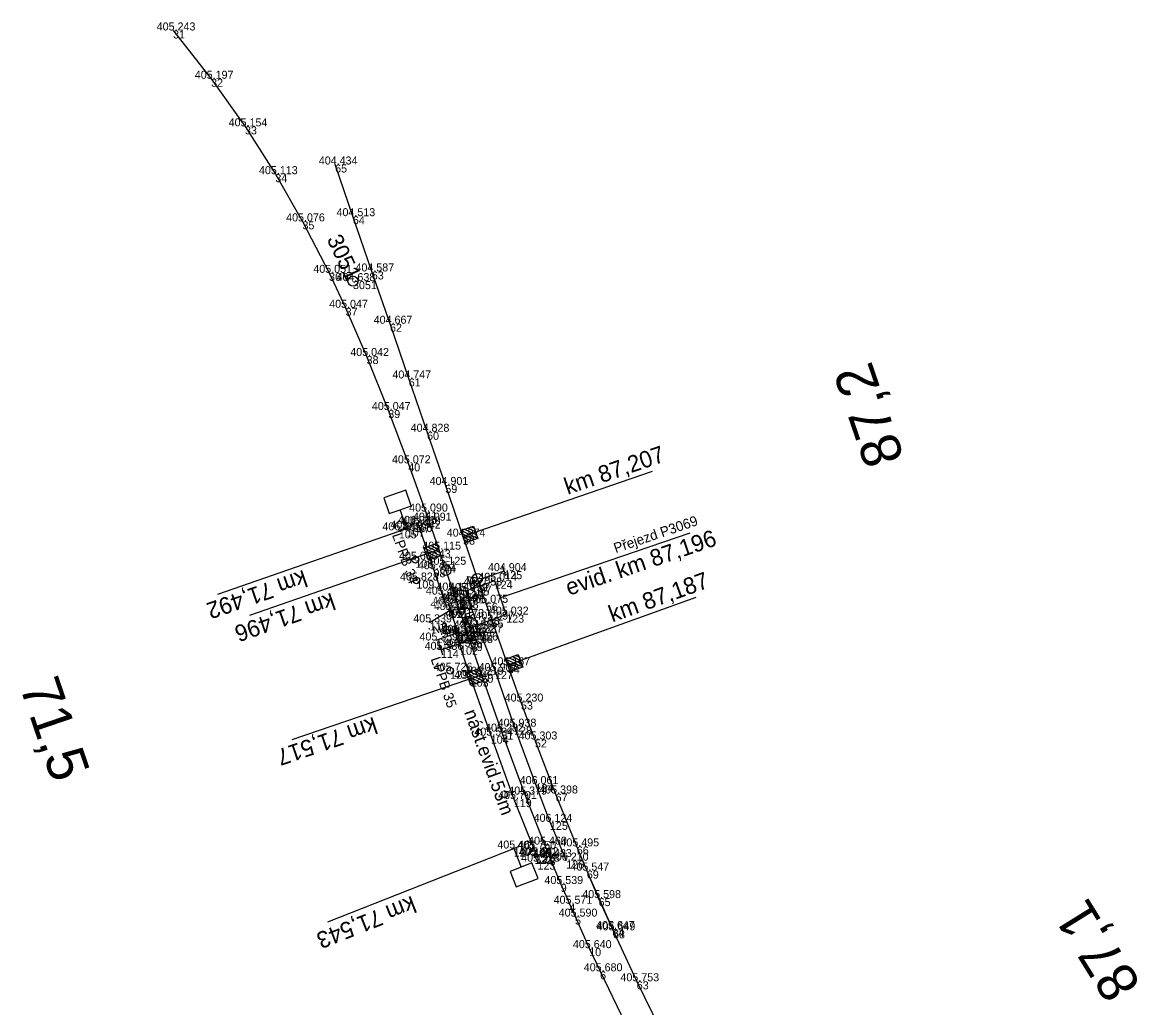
# Model space of a CAD drawing. Extents: x -663503 to -663109, y -1005607 to -1005191.
# Drawn here: x -663503.2 to -663335.9, y -1005338.4 to -1005190.7 of the extents above; entities that cross this region are included whole.
import ezdxf

# ---------------------------------------------------------------- set-up
doc = ezdxf.new("R2010")
doc.units = 0
for name, color, linetype in [('Vrstva 1', 7, 'Continuous'), ('Vrstva 14', 7, 'Continuous'), ('Vrstva 17', 7, 'Continuous'), ('Vrstva 27', 7, 'Continuous'), ('Vrstva 3', 7, 'Continuous'), ('Vrstva 4', 7, 'Continuous'), ('Vrstva 51', 7, 'Continuous'), ('Vrstva 60', 7, 'Continuous'), ('Vrstva 61', 7, 'Continuous'), ('Vrstva 63', 7, 'Continuous'), ('Vrstva 7', 7, 'Continuous')]:
    doc.layers.add(name, color=color, linetype=linetype)

msp = doc.modelspace()

# ---------------------------------------------------------------- linework, layer by layer
at = {"layer": 'Vrstva 1'}
for points in [[(-663480.6, -1005191.9), (-663474.89, -1005199.14), (-663469.81, -1005206.28), (-663465.26, -1005213.44), (-663461.19, -1005220.52), (-663457.21, -1005228.23), (-663454.72, -1005233.47), (-663451.57, -1005240.7), (-663448.32, -1005248.79), (-663445.32, -1005256.78), (-663442.74, -1005264.01), (-663442.26, -1005265.38), (-663440.75, -1005269.72), (-663439.97, -1005271.99), (-663438.65, -1005275.86), (-663438.1, -1005277.49), (-663437.3, -1005279.82), (-663436.51, -1005282.15), (-663435.97, -1005283.72), (-663434.35, -1005288.47), (-663431.35, -1005296.99), (-663427.86, -1005306.43), (-663424.9, -1005313.94), (-663424.14, -1005315.79), (-663422.45, -1005319.84), (-663421.16, -1005322.8), (-663420.31, -1005324.72), (-663418.18, -1005329.45), (-663416.55, -1005332.92), (-663412.77, -1005340.68)], [(-663407.43, -1005341.75), (-663411.05, -1005334.42), (-663414.7, -1005326.58), (-663416.77, -1005321.95), (-663420.04, -1005314.2), (-663423.22, -1005306.27), (-663426.32, -1005298.17), (-663428.42, -1005292.49), (-663430.38, -1005287.06), (-663432.81, -1005280.21), (-663433.69, -1005277.69), (-663434.59, -1005275.1), (-663437.1, -1005267.77), (-663439.76, -1005260.02), (-663442.5, -1005252.05), (-663445.25, -1005244.06), (-663448.06, -1005235.86), (-663450.79, -1005228.02), (-663453.63, -1005219.74), (-663456.29, -1005211.99)], [(-663414.61, -1005326.78), (-663418.54, -1005317.83)]]:
    msp.add_lwpolyline(points, dxfattribs=at)
at = {"layer": 'Vrstva 14'}
for points in [[(-663443.83, -1005265.96), (-663441.53, -1005272.66), (-663440.24, -1005276.46), (-663439.54, -1005278.4)], [(-663438.18, -1005282.37), (-663437.55, -1005284.27), (-663435.95, -1005289.06), (-663432.95, -1005297.6), (-663429.49, -1005307.1), (-663426.51, -1005314.57), (-663426.15, -1005315.52), (-663426.39, -1005315.63), (-663425.94, -1005316.49)]]:
    msp.add_lwpolyline(points, dxfattribs=at)
at = {"layer": 'Vrstva 17'}
msp.add_line((-663446.74, -1005266.83), (-663444.4, -1005265.86), dxfattribs=at)
msp.add_lwpolyline([(-663434.53, -1005282.14), (-663432.31, -1005287.92), (-663429.46, -1005296.25), (-663426.26, -1005304.86), (-663424.07, -1005310.52), (-663421.63, -1005316.33)], dxfattribs=at)
at = {"layer": 'Vrstva 27'}
for p, q in [((-663444.28, -1005271.18), (-663444.24, -1005271.28)), ((-663439.06, -1005287.83), (-663439.03, -1005287.92))]:
    msp.add_line(p, q, dxfattribs=at)
for centre in [(-663444.26, -1005271.23), (-663439.05, -1005287.87)]:
    msp.add_circle(centre, 0.5, dxfattribs=at)
at = {"layer": 'Vrstva 3'}
for p, q in [((-663408.73, -1005258.03), (-663437.1, -1005267.77)), ((-663435.06, -1005267.57), (-663436.92, -1005266.65)), ((-663435.23, -1005267.06), (-663436.42, -1005266.48)), ((-663435.4, -1005266.56), (-663435.92, -1005266.31)), ((-663434.88, -1005268.07), (-663437.43, -1005266.83)), ((-663435.39, -1005268.24), (-663437.25, -1005267.33)), ((-663435.89, -1005268.41), (-663437.08, -1005267.83)), ((-663436.39, -1005268.58), (-663436.91, -1005268.33)), ((-663469.1, -1005279.53), (-663440.75, -1005269.72)), ((-663442.97, -1005269.43), (-663440.42, -1005270.67)), ((-663442.79, -1005269.93), (-663440.92, -1005270.84)), ((-663442.47, -1005269.26), (-663440.6, -1005270.17)), ((-663441.96, -1005269.09), (-663440.77, -1005269.67)), ((-663441.46, -1005268.91), (-663440.94, -1005269.16)), ((-663442.62, -1005270.43), (-663441.42, -1005271.02)), ((-663442.45, -1005270.94), (-663441.93, -1005271.19)), ((-663402.17, -1005276.87), (-663430.38, -1005287.06)), ((-663428.16, -1005287.32), (-663430.72, -1005286.12)), ((-663428.66, -1005287.5), (-663430.54, -1005286.62)), ((-663428.34, -1005286.82), (-663430.23, -1005285.94)), ((-663428.52, -1005286.32), (-663429.73, -1005285.76)), ((-663428.7, -1005285.83), (-663429.23, -1005285.58)), ((-663436.57, -1005288.17), (-663434.03, -1005289.42)), ((-663436.07, -1005288), (-663434.2, -1005288.91)), ((-663435.56, -1005287.83), (-663434.37, -1005288.41)), ((-663435.06, -1005287.66), (-663434.54, -1005287.91)), ((-663429.16, -1005287.68), (-663430.36, -1005287.12)), ((-663429.66, -1005287.86), (-663430.18, -1005287.62)), ((-663462.74, -1005298.18), (-663434.35, -1005288.47)), ((-663436.4, -1005288.67), (-663434.53, -1005289.59)), ((-663436.22, -1005289.17), (-663435.03, -1005289.76)), ((-663436.05, -1005289.68), (-663435.53, -1005289.93))]:
    msp.add_line(p, q, dxfattribs=at)
for points in [[(-663436.78, -1005268.72), (-663437.43, -1005266.83), (-663435.53, -1005266.18), (-663434.88, -1005268.07)], [(-663441.08, -1005268.78), (-663440.42, -1005270.67), (-663442.31, -1005271.32), (-663442.97, -1005269.43)], [(-663430.04, -1005288), (-663430.72, -1005286.12), (-663428.84, -1005285.44), (-663428.16, -1005287.32)], [(-663434.68, -1005287.52), (-663434.03, -1005289.42), (-663435.92, -1005290.06), (-663436.57, -1005288.17)]]:
    msp.add_lwpolyline(points, close=True, dxfattribs=at)
at = {"layer": 'Vrstva 4'}
for p, q in [((-663403.11, -1005267.23), (-663431.5, -1005276.92)), ((-663430.67, -1005273.67), (-663431.17, -1005272.2)), ((-663435.27, -1005274.64), (-663435.71, -1005274.42)), ((-663436.06, -1005283.04), (-663435.62, -1005283.26)), ((-663440.66, -1005284), (-663440.17, -1005285.48))]:
    msp.add_line(p, q, dxfattribs=at)
for points in [[(-663430.92, -1005272.94), (-663434.21, -1005274.06), (-663435.79, -1005275.64), (-663436.44, -1005273.75), (-663434.21, -1005274.06)], [(-663432.36, -1005274.38), (-663436.75, -1005275.94), (-663436.5, -1005276.59), (-663434.99, -1005281), (-663430.63, -1005279.46), (-663432.36, -1005274.38)], [(-663439.28, -1005277.96), (-663437.72, -1005282.62), (-663435.9, -1005282), (-663436.06, -1005281.51), (-663437.45, -1005277.35), (-663439.28, -1005277.96)], [(-663440.42, -1005284.74), (-663437.12, -1005283.62), (-663435.54, -1005282.04), (-663434.89, -1005283.93), (-663437.12, -1005283.62)]]:
    msp.add_lwpolyline(points, dxfattribs=at)
for centre in [(-663435.49, -1005274.53), (-663435.84, -1005283.15)]:
    msp.add_circle(centre, 0.248, dxfattribs=at)
at = {"layer": 'Vrstva 51'}
for points in [[(-663434.99, -1005281), (-663436.06, -1005281.51), (-663437.45, -1005277.35), (-663436.5, -1005276.59), (-663434.99, -1005281)], [(-663442.12, -1005280.62), (-663439.05, -1005278.78), (-663437.89, -1005282.19), (-663441.18, -1005283.34)]]:
    msp.add_lwpolyline(points, dxfattribs=at)
at = {"layer": 'Vrstva 60'}
for p, q in [((-663480.6, -1005191.9), (-663480.6, -1005191.9)), ((-663474.89, -1005199.14), (-663474.89, -1005199.14)), ((-663469.81, -1005206.28), (-663469.81, -1005206.28)), ((-663456.29, -1005211.99), (-663456.29, -1005211.99)), ((-663465.26, -1005213.44), (-663465.26, -1005213.44)), ((-663453.63, -1005219.74), (-663453.63, -1005219.74)), ((-663461.19, -1005220.52), (-663461.19, -1005220.52)), ((-663450.79, -1005228.02), (-663450.79, -1005228.02)), ((-663457.21, -1005228.23), (-663457.21, -1005228.23)), ((-663453.61, -1005229.47), (-663453.61, -1005229.47)), ((-663454.72, -1005233.47), (-663454.72, -1005233.47)), ((-663448.06, -1005235.86), (-663448.06, -1005235.86)), ((-663451.57, -1005240.7), (-663451.57, -1005240.7)), ((-663445.25, -1005244.06), (-663445.25, -1005244.06)), ((-663448.32, -1005248.79), (-663448.32, -1005248.79)), ((-663442.5, -1005252.05), (-663442.5, -1005252.05)), ((-663445.32, -1005256.78), (-663445.32, -1005256.78)), ((-663439.76, -1005260.02), (-663439.76, -1005260.02)), ((-663442.74, -1005264.01), (-663442.74, -1005264.01)), ((-663445.55, -1005266.57), (-663445.55, -1005266.57)), ((-663444.4, -1005265.86), (-663444.4, -1005265.86)), ((-663443.83, -1005265.96), (-663443.83, -1005265.96)), ((-663442.26, -1005265.38), (-663442.26, -1005265.38)), ((-663446.74, -1005266.83), (-663446.74, -1005266.83)), ((-663437.1, -1005267.77), (-663437.1, -1005267.77)), ((-663440.75, -1005269.72), (-663440.75, -1005269.72)), ((-663444.26, -1005271.23), (-663444.26, -1005271.23)), ((-663441.53, -1005272.66), (-663441.53, -1005272.66)), ((-663439.97, -1005271.99), (-663439.97, -1005271.99)), ((-663430.92, -1005272.94), (-663430.92, -1005272.94)), ((-663444.1, -1005274.35), (-663444.1, -1005274.35)), ((-663432.36, -1005274.38), (-663432.36, -1005274.38)), ((-663440.24, -1005276.46), (-663440.24, -1005276.46)), ((-663438.65, -1005275.86), (-663438.65, -1005275.86)), ((-663436.75, -1005275.94), (-663436.75, -1005275.94)), ((-663436.5, -1005276.59), (-663436.5, -1005276.59)), ((-663434.59, -1005275.1), (-663434.59, -1005275.1)), ((-663439.28, -1005277.96), (-663439.28, -1005277.96)), ((-663438.1, -1005277.49), (-663438.1, -1005277.49)), ((-663437.45, -1005277.35), (-663437.45, -1005277.35)), ((-663433.69, -1005277.69), (-663433.69, -1005277.69)), ((-663439.54, -1005278.4), (-663439.54, -1005278.4)), ((-663439.05, -1005278.78), (-663439.05, -1005278.78)), ((-663437.3, -1005279.82), (-663437.3, -1005279.82)), ((-663430.63, -1005279.46), (-663430.63, -1005279.46)), ((-663442.12, -1005280.62), (-663442.12, -1005280.62)), ((-663436.06, -1005281.51), (-663436.06, -1005281.51)), ((-663434.99, -1005281), (-663434.99, -1005281)), ((-663432.81, -1005280.21), (-663432.81, -1005280.21)), ((-663441.18, -1005283.34), (-663441.18, -1005283.34)), ((-663438.18, -1005282.37), (-663438.18, -1005282.37)), ((-663437.89, -1005282.19), (-663437.89, -1005282.19)), ((-663437.72, -1005282.62), (-663437.72, -1005282.62)), ((-663436.51, -1005282.15), (-663436.51, -1005282.15)), ((-663435.9, -1005282), (-663435.9, -1005282)), ((-663434.53, -1005282.14), (-663434.53, -1005282.14)), ((-663440.42, -1005284.74), (-663440.42, -1005284.74)), ((-663437.55, -1005284.27), (-663437.55, -1005284.27)), ((-663435.97, -1005283.72), (-663435.97, -1005283.72)), ((-663439.05, -1005287.87), (-663439.05, -1005287.87)), ((-663432.31, -1005287.92), (-663432.31, -1005287.92)), ((-663430.38, -1005287.06), (-663430.38, -1005287.06)), ((-663435.95, -1005289.06), (-663435.95, -1005289.06)), ((-663434.35, -1005288.47), (-663434.35, -1005288.47)), ((-663428.42, -1005292.49), (-663428.42, -1005292.49)), ((-663429.46, -1005296.25), (-663429.46, -1005296.25)), ((-663432.95, -1005297.6), (-663432.95, -1005297.6)), ((-663431.35, -1005296.99), (-663431.35, -1005296.99)), ((-663426.32, -1005298.17), (-663426.32, -1005298.17)), ((-663426.26, -1005304.86), (-663426.26, -1005304.86)), ((-663427.86, -1005306.43), (-663427.86, -1005306.43)), ((-663423.22, -1005306.27), (-663423.22, -1005306.27)), ((-663429.49, -1005307.1), (-663429.49, -1005307.1)), ((-663424.07, -1005310.52), (-663424.07, -1005310.52)), ((-663429.51, -1005314.52), (-663429.51, -1005314.52)), ((-663426.51, -1005314.57), (-663426.51, -1005314.57)), ((-663424.9, -1005313.94), (-663424.9, -1005313.94)), ((-663420.04, -1005314.2), (-663420.04, -1005314.2)), ((-663426.39, -1005315.63), (-663426.39, -1005315.63)), ((-663426.15, -1005315.52), (-663426.15, -1005315.52)), ((-663425.94, -1005316.49), (-663425.94, -1005316.49)), ((-663424.14, -1005315.79), (-663424.14, -1005315.79)), ((-663421.63, -1005316.33), (-663421.63, -1005316.33)), ((-663418.54, -1005317.83), (-663418.54, -1005317.83)), ((-663422.45, -1005319.84), (-663422.45, -1005319.84)), ((-663421.16, -1005322.8), (-663421.16, -1005322.8)), ((-663416.77, -1005321.95), (-663416.77, -1005321.95)), ((-663420.31, -1005324.72), (-663420.31, -1005324.72)), ((-663414.7, -1005326.58), (-663414.7, -1005326.58)), ((-663414.61, -1005326.78), (-663414.61, -1005326.78)), ((-663418.18, -1005329.45), (-663418.18, -1005329.45)), ((-663416.55, -1005332.92), (-663416.55, -1005332.92)), ((-663411.05, -1005334.42), (-663411.05, -1005334.42))]:
    msp.add_line(p, q, dxfattribs=at)
at = {"layer": 'Vrstva 63'}
msp.add_line((-663453.64, -1005229.42), (-663453.59, -1005229.51), dxfattribs=at)
msp.add_circle((-663453.61, -1005229.47), 0.756, dxfattribs=at)
at = {"layer": 'Vrstva 7'}
for p, q in [((-663473.9, -1005276.38), (-663445.55, -1005266.57)), ((-663446.26, -1005266.82), (-663444.84, -1005266.33)), ((-663444.11, -1005274.3), (-663444.08, -1005274.4)), ((-663457.41, -1005325.53), (-663429.51, -1005314.52)), ((-663428.81, -1005314.25), (-663430.21, -1005314.8))]:
    msp.add_line(p, q, dxfattribs=at)
for points in [[(-663445.55, -1005266.57), (-663446.53, -1005263.74), (-663444.88, -1005263.16), (-663445.7, -1005260.8), (-663449.01, -1005261.95), (-663448.19, -1005264.31), (-663446.53, -1005263.74)], [(-663429.51, -1005314.52), (-663428.41, -1005317.31), (-663430.04, -1005317.95), (-663429.12, -1005320.28), (-663425.86, -1005318.99), (-663426.78, -1005316.67), (-663428.41, -1005317.31)]]:
    msp.add_lwpolyline(points, dxfattribs=at)
for centre, radius in [((-663439.68, -1005272.84), 0.75), ((-663434.95, -1005274.05), 0.75), ((-663444.1, -1005274.35), 0.5)]:
    msp.add_circle(centre, radius, dxfattribs=at)

# ---------------------------------------------------------------- texts
at = {"layer": 'Vrstva 14'}
msp.add_text('nást.evid.53m', height=2, rotation=290.0242, dxfattribs=at).set_placement((-663436.97, -1005294.07))
at = {"layer": 'Vrstva 27'}
for s, rotation, p in [('LPPB 34', 289.0902, (-663447.77, -1005267.52)), ('LPPB 35', 288.8756, (-663441.98, -1005286.09))]:
    msp.add_text(s, height=1.5, rotation=rotation, dxfattribs=at).set_placement(p)
at = {"layer": 'Vrstva 3'}
for s, rotation, p in [('km 87,207', 18.9388, (-663421.42, -1005261.51)), ('km 87,187', 19.8687, (-663414.72, -1005280.64)), ('km 71,496', 199.0902, (-663456.84, -1005276.15)), ('km 71,517', 198.8756, (-663450.52, -1005294.74))]:
    msp.add_text(s, height=2.5, rotation=rotation, dxfattribs=at).set_placement(p)
at = {"layer": 'Vrstva 4'}
for s, height, p in [('Přejezd P3069', 1.5, (-663414.21, -1005270.25)), ('evid. km 87,196', 2.5, (-663421.22, -1005276.65))]:
    msp.add_text(s, height=height, rotation=18.8468, dxfattribs=at).set_placement(p)
at = {"layer": 'Vrstva 51'}
for rotation, p in [(288.9519, (-663437.12, -1005278.24)), (197.9705, (-663439.61, -1005280.62))]:
    msp.add_text('živ.', height=1.5, rotation=rotation, dxfattribs=at).set_placement(p)
at = {"layer": 'Vrstva 60'}
for s, p in [('31', (-663480.6, -1005193.1)), ('32', (-663474.89, -1005200.34)), ('33', (-663469.81, -1005207.48)), ('65', (-663456.29, -1005213.19)), ('34', (-663465.26, -1005214.64)), ('64', (-663453.63, -1005220.94)), ('35', (-663461.19, -1005221.71)), ('63', (-663450.79, -1005229.22)), ('36', (-663457.21, -1005229.43)), ('3051', (-663453.61, -1005230.67)), ('37', (-663454.72, -1005234.67)), ('62', (-663448.06, -1005237.06)), ('38', (-663451.57, -1005241.9)), ('61', (-663445.25, -1005245.26)), ('39', (-663448.32, -1005249.99)), ('60', (-663442.5, -1005253.25)), ('40', (-663445.32, -1005257.98)), ('59', (-663439.76, -1005261.22)), ('41', (-663442.74, -1005265.21)), ('107', (-663445.55, -1005267.77)), ('106', (-663444.4, -1005267.06)), ('97', (-663443.83, -1005267.17)), ('42', (-663442.26, -1005266.58)), ('105', (-663446.74, -1005268.03)), ('58', (-663437.1, -1005268.97)), ('43', (-663440.75, -1005270.92)), ('108', (-663444.26, -1005272.43)), ('98', (-663441.53, -1005273.86)), ('44', (-663439.97, -1005273.19)), ('125', (-663430.92, -1005274.14)), ('109', (-663444.1, -1005275.55)), ('124', (-663432.36, -1005275.58)), ('99', (-663440.24, -1005277.66)), ('45', (-663438.65, -1005277.06)), ('120', (-663436.75, -1005277.14)), ('121', (-663436.5, -1005277.79)), ('57', (-663434.59, -1005276.3)), ('100', (-663439.54, -1005279.59)), ('119', (-663439.28, -1005279.16)), ('46', (-663438.1, -1005278.69)), ('118', (-663437.45, -1005278.55)), ('56', (-663433.69, -1005278.89)), ('111', (-663439.05, -1005279.97)), ('47', (-663437.3, -1005281.02)), ('123', (-663430.63, -1005280.66)), ('110', (-663442.12, -1005281.82)), ('117', (-663436.06, -1005282.71)), ('122', (-663434.99, -1005282.2)), ('55', (-663432.81, -1005281.42)), ('113', (-663441.18, -1005284.54)), ('101', (-663438.18, -1005283.57)), ('112', (-663437.89, -1005283.39)), ('115', (-663437.72, -1005283.82)), ('48', (-663436.51, -1005283.35)), ('116', (-663435.9, -1005283.2)), ('126', (-663434.53, -1005283.34)), ('114', (-663440.42, -1005285.94)), ('102', (-663437.55, -1005285.47)), ('49', (-663435.97, -1005284.92)), ('129', (-663439.05, -1005289.07)), ('127', (-663432.31, -1005289.12)), ('54', (-663430.38, -1005288.26)), ('103', (-663435.95, -1005290.26)), ('50', (-663434.35, -1005289.67)), ('53', (-663428.42, -1005293.69)), ('128', (-663429.46, -1005297.45)), ('104', (-663432.95, -1005298.8)), ('51', (-663431.35, -1005298.2)), ('52', (-663426.32, -1005299.37)), ('124', (-663426.26, -1005306.06)), ('1', (-663427.86, -1005307.63)), ('67', (-663423.22, -1005307.47)), ('119', (-663429.49, -1005308.31)), ('125', (-663424.07, -1005311.72)), ('127', (-663429.51, -1005315.72)), ('120', (-663426.51, -1005315.77)), ('2', (-663424.9, -1005315.14)), ('66', (-663420.04, -1005315.4)), ('122', (-663426.39, -1005316.83)), ('121', (-663426.15, -1005316.72)), ('123', (-663425.94, -1005317.69)), ('3', (-663424.14, -1005316.99)), ('126', (-663421.63, -1005317.53)), ('69', (-663418.54, -1005319.03)), ('9', (-663422.45, -1005321.04)), ('4', (-663421.16, -1005324)), ('65', (-663416.77, -1005323.15)), ('5', (-663420.31, -1005325.92)), ('64', (-663414.7, -1005327.78)), ('68', (-663414.61, -1005327.98)), ('10', (-663418.18, -1005330.65)), ('6', (-663416.55, -1005334.12)), ('63', (-663411.05, -1005335.62))]:
    msp.add_text(s, height=1.2, dxfattribs=at).set_placement(p)
at = {"layer": 'Vrstva 61'}
for s, p in [('405.243', (-663483.05, -1005191.9)), ('405.197', (-663477.34, -1005199.14)), ('405.154', (-663472.26, -1005206.28)), ('404.434', (-663458.74, -1005211.99)), ('405.113', (-663467.71, -1005213.44)), ('405.076', (-663463.64, -1005220.52)), ('404.513', (-663456.08, -1005219.74)), ('405.051', (-663459.56, -1005228.23)), ('404.587', (-663453.24, -1005228.02)), ('404.638', (-663456.07, -1005229.47)), ('405.047', (-663457.18, -1005233.47)), ('404.667', (-663450.51, -1005235.86)), ('405.042', (-663454.02, -1005240.7)), ('404.747', (-663447.7, -1005244.06)), ('405.047', (-663450.78, -1005248.79)), ('404.828', (-663444.96, -1005252.05)), ('405.072', (-663447.77, -1005256.78)), ('404.901', (-663442.12, -1005260.02)), ('405.090', (-663445.19, -1005264.01)), ('406.085', (-663446.86, -1005265.86)), ('405.380', (-663446.28, -1005265.96)), ('405.091', (-663444.62, -1005265.38)), ('406.085', (-663449.2, -1005266.83)), ('405.199', (-663448.01, -1005266.57)), ('404.974', (-663439.55, -1005267.77)), ('405.600', (-663446.71, -1005271.23)), ('405.115', (-663443.21, -1005269.72)), ('405.451', (-663443.89, -1005272.66)), ('405.125', (-663442.43, -1005271.99)), ('405.828', (-663446.55, -1005274.35)), ('405.014', (-663434.82, -1005274.38)), ('404.904', (-663433.37, -1005272.94)), ('405.149', (-663441.1, -1005275.86)), ('405.099', (-663439.21, -1005275.94)), ('405.053', (-663437.04, -1005275.1)), ('405.496', (-663442.69, -1005276.46)), ('405.159', (-663440.55, -1005277.49)), ('405.147', (-663439.9, -1005277.35)), ('405.105', (-663438.96, -1005276.59)), ('405.075', (-663436.15, -1005277.69)), ('405.210', (-663441.99, -1005278.4)), ('405.180', (-663441.73, -1005277.96)), ('405.180', (-663441.5, -1005278.78)), ('405.032', (-663433.08, -1005279.46)), ('405.339', (-663444.57, -1005280.62)), ('405.173', (-663439.75, -1005279.82)), ('405.168', (-663437.44, -1005281)), ('405.097', (-663435.26, -1005280.21)), ('405.270', (-663440.63, -1005282.37)), ('405.195', (-663440.34, -1005282.19)), ('405.199', (-663440.17, -1005282.62)), ('405.182', (-663438.96, -1005282.15)), ('405.159', (-663438.51, -1005281.51)), ('405.165', (-663438.36, -1005282)), ('405.887', (-663436.98, -1005282.14)), ('405.359', (-663443.64, -1005283.34)), ('405.556', (-663440, -1005284.27)), ('405.188', (-663438.43, -1005283.72)), ('405.336', (-663442.87, -1005284.74)), ('405.726', (-663441.5, -1005287.87)), ('405.907', (-663434.77, -1005287.92)), ('405.167', (-663432.84, -1005287.06)), ('405.546', (-663438.4, -1005289.06)), ('405.219', (-663436.81, -1005288.47)), ('405.230', (-663430.87, -1005292.49)), ('405.938', (-663431.91, -1005296.25)), ('405.584', (-663435.41, -1005297.6)), ('405.282', (-663433.8, -1005296.99)), ('405.303', (-663428.77, -1005298.17)), ('406.061', (-663428.61, -1005304.86)), ('405.398', (-663425.68, -1005306.27)), ('405.701', (-663431.85, -1005307.1)), ('405.379', (-663430.32, -1005306.43)), ('406.124', (-663426.52, -1005310.52)), ('405.467', (-663431.96, -1005314.52)), ('405.750', (-663428.96, -1005314.57)), ('405.460', (-663427.35, -1005313.94)), ('405.495', (-663422.5, -1005314.2)), ('405.641', (-663428.75, -1005315.63)), ('405.642', (-663428.59, -1005315.52)), ('405.483', (-663426.59, -1005315.79)), ('406.210', (-663424.08, -1005316.33)), ('405.528', (-663428.39, -1005316.49)), ('405.547', (-663420.99, -1005317.83)), ('405.539', (-663424.9, -1005319.84)), ('405.571', (-663423.52, -1005322.8)), ('405.598', (-663419.22, -1005321.95)), ('405.590', (-663422.76, -1005324.72)), ('405.647', (-663417.15, -1005326.58)), ('405.649', (-663417.07, -1005326.78)), ('405.640', (-663420.63, -1005329.45)), ('405.680', (-663419, -1005332.92)), ('405.753', (-663413.5, -1005334.42))]:
    msp.add_text(s, height=1.2, dxfattribs=at).set_placement(p)
at = {"layer": 'Vrstva 63'}
msp.add_text('3051', height=2.4, rotation=295.341, dxfattribs=at).set_placement((-663457.59, -1005223.18))
at = {"layer": 'Vrstva 7'}
for s, height, rotation, p in [('87,2', 6, 108.9472, (-663370.89, -1005256.03)), ('km 71,492', 2.5, 199.0902, (-663461.03, -1005272.72)), ('71,5', 6, 288.8554, (-663503.67, -1005290.14)), ('km 71,543', 2.5, 201.5377, (-663444.79, -1005321.56)), ('87,1', 6, 121.8296, (-663335.29, -1005334.93))]:
    msp.add_text(s, height=height, rotation=rotation, dxfattribs=at).set_placement(p)

doc.saveas('drawing.dxf')
